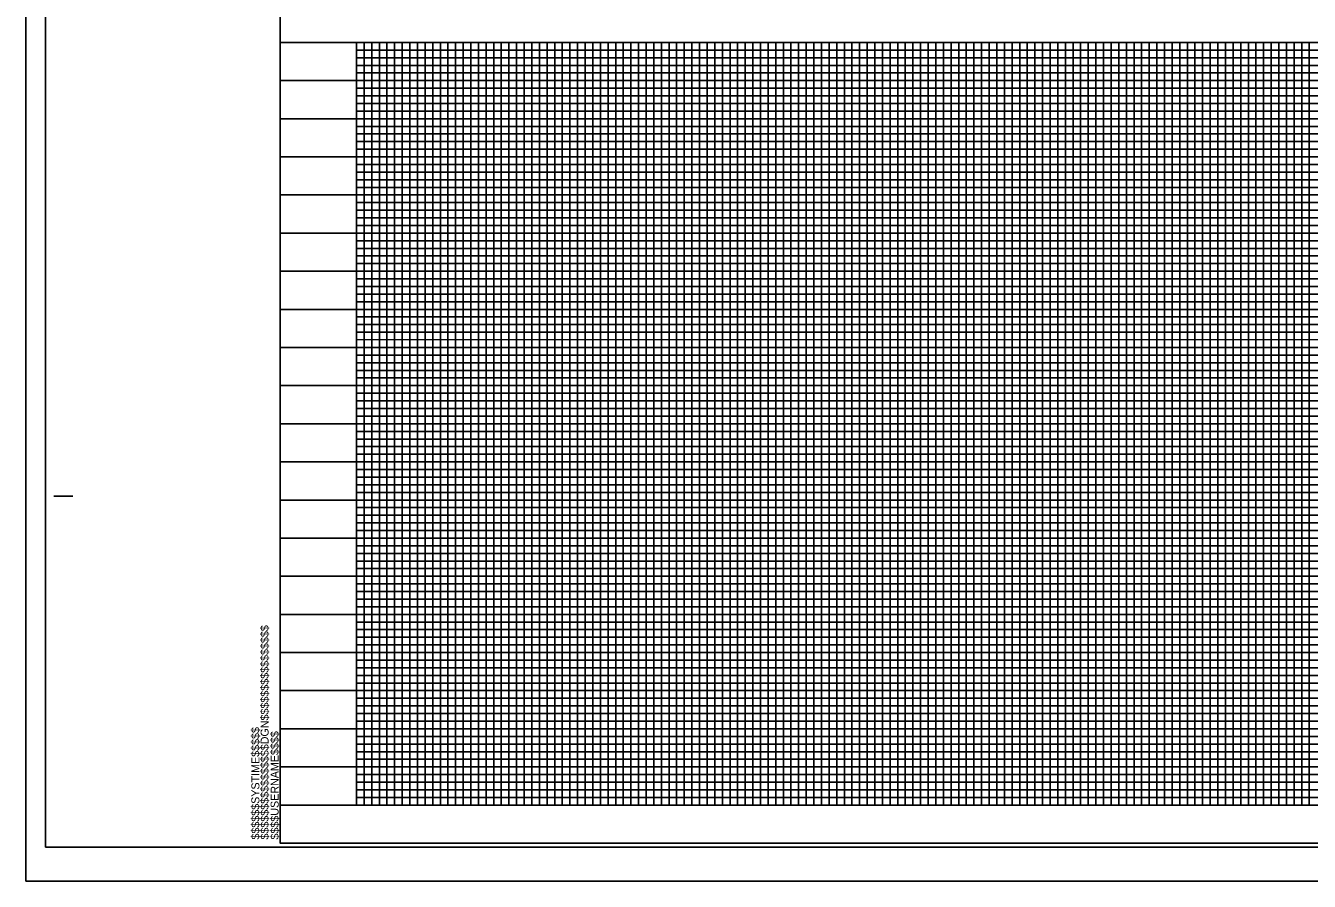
# Model space of a CAD drawing. Extents: x 2331575 to 2333259, y 609001 to 610101.
# Drawn here: x 2331575 to 2332417, y 609001 to 609562 of the extents above; entities that cross this region are included whole.
import ezdxf

# ---------------------------------------------------------------- set-up
doc = ezdxf.new("R2010")
doc.units = 0
for name, color, linetype in [('Sheet Cutting Line CELL', 7, 'Continuous'), ('Sheet DOT Grid CELL', 7, 'Continuous'), ('Sheet Layout Profile Border Port 2', 7, 'Continuous'), ('Sheet Plot Border Inside CELL', 7, 'Continuous'), ('Sheet Plot Border Outside CELL', 7, 'Continuous'), ('Sheet Profile CELL', 7, 'Continuous'), ('Sheet Profile Grid Major CELL', 7, 'Continuous'), ('Sheet Profile Grid Middle CELL', 7, 'Continuous'), ('Sheet Profile Grid Minor CELL', 7, 'Continuous')]:
    doc.layers.add(name, color=color, linetype=linetype)

msp = doc.modelspace()

# ---------------------------------------------------------------- linework, layer by layer
at = {"layer": 'Sheet Cutting Line CELL'}
for p, q in [((2331575.23, 610101.48), (2331575.23, 609001.48)), ((2331575.23, 609001.48), (2333259.23, 609001.48))]:
    msp.add_line(p, q, dxfattribs=at)
at = {"layer": 'Sheet DOT Grid CELL'}
for p, q in [((2331742.23, 609551.48), (2333242.11, 609551.48)), ((2331792.23, 609551.48), (2331792.23, 609051.48)), ((2331842.23, 609551.48), (2331842.23, 609051.48)), ((2331892.23, 609551.48), (2331892.23, 609051.48)), ((2331942.23, 609551.48), (2331942.23, 609051.48)), ((2331992.23, 609551.48), (2331992.23, 609051.48)), ((2332042.23, 609551.48), (2332042.23, 609051.48)), ((2332092.23, 609551.48), (2332092.23, 609051.48)), ((2332142.23, 609551.48), (2332142.23, 609051.48)), ((2332192.23, 609551.48), (2332192.23, 609051.48)), ((2332242.23, 609551.48), (2332242.23, 609051.48)), ((2332292.23, 609551.48), (2332292.23, 609051.48)), ((2332342.23, 609551.48), (2332342.23, 609051.48)), ((2332392.23, 609551.48), (2332392.23, 609051.48)), ((2331742.23, 609501.48), (2333242.11, 609501.48)), ((2331742.23, 609451.48), (2333242.11, 609451.48)), ((2331742.23, 609401.48), (2333242.11, 609401.48)), ((2331742.23, 609351.48), (2333242.11, 609351.48)), ((2331742.23, 609301.48), (2333242.11, 609301.48)), ((2331742.23, 609251.48), (2333242.11, 609251.48)), ((2331742.23, 609201.48), (2333242.11, 609201.48)), ((2331742.23, 609151.48), (2333242.11, 609151.48)), ((2331742.23, 609101.48), (2333242.11, 609101.48))]:
    msp.add_line(p, q, dxfattribs=at)
at = {"layer": 'Sheet Layout Profile Border Port 2'}
msp.add_lwpolyline([(2331792.23, 609551.48), (2333192.23, 609551.48), (2333192.23, 609051.48), (2331792.23, 609051.48)], close=True, dxfattribs=at)
at = {"layer": 'Sheet Plot Border Inside CELL'}
msp.add_lwpolyline([(2331588.23, 609023.93), (2333254.73, 609023.93), (2333254.73, 610079.03), (2331588.23, 610079.03)], close=True, dxfattribs=at)
at = {"layer": 'Sheet Plot Border Outside CELL'}
msp.add_lwpolyline([(2331575.23, 609001.48), (2333259.23, 609001.48), (2333259.23, 610101.48), (2331575.23, 610101.48)], close=True, dxfattribs=at)
at = {"layer": 'Sheet Profile CELL'}
for p, q in [((2331742.23, 609551.48), (2333242.23, 609551.48)), ((2331593.73, 609253.98), (2331606.23, 609253.98)), ((2333242.23, 609051.48), (2331742.23, 609051.48)), ((2331742.23, 609026.48), (2333242.23, 609026.48)), ((2331742.23, 609026.48), (2331742.23, 609026.48)), ((2331742.23, 609026.48), (2331742.23, 609026.48)), ((2331742.23, 609026.48), (2331742.23, 609026.48)), ((2331742.23, 609026.48), (2331742.23, 609026.48)), ((2331742.23, 609026.48), (2331742.23, 609026.48)), ((2331742.23, 609026.48), (2331742.23, 609026.48)), ((2331742.23, 609026.48), (2331742.23, 609026.48))]:
    msp.add_line(p, q, dxfattribs=at)
msp.add_lwpolyline([(2333242.23, 610076.48), (2331742.23, 610076.48), (2331742.23, 609026.48), (2333242.23, 609026.48)], close=True, dxfattribs=at)
msp.add_lwpolyline([(2331779.73, 609026.48), (2331779.73, 609026.48)], dxfattribs=at)
at = {"layer": 'Sheet Profile Grid Major CELL'}
for p, q in [((2332242.23, 609551.48), (2332292.23, 609551.48)), ((2332342.23, 609551.48), (2332392.23, 609551.48)), ((2331742.23, 609051.48), (2331742.23, 609051.48))]:
    msp.add_line(p, q, dxfattribs=at)
for points in [[(2331792.23, 609551.48), (2331792.23, 609051.48), (2331842.23, 609051.48), (2331842.23, 609551.48), (2331892.23, 609551.48), (2331892.23, 609051.48), (2331942.23, 609051.48), (2331942.23, 609551.48), (2331992.23, 609551.48), (2331992.23, 609051.48), (2332042.23, 609051.48), (2332042.23, 609551.48), (2332092.23, 609551.48), (2332092.23, 609051.48), (2332142.23, 609051.48), (2332142.23, 609551.48), (2332192.23, 609551.48), (2332192.23, 609051.48), (2332242.23, 609051.48), (2332242.23, 609551.48), (2332292.23, 609551.48), (2332292.23, 609051.48), (2332342.23, 609051.48), (2332342.23, 609551.48), (2332392.23, 609551.48), (2332392.23, 609051.48), (2332442.23, 609051.48)], [(2333242.23, 609501.48), (2331742.23, 609501.48)], [(2333242.23, 609451.48), (2331742.23, 609451.48), (2331742.23, 609401.48), (2333242.23, 609401.48)], [(2333242.23, 609351.48), (2331742.23, 609351.48), (2331742.23, 609301.48), (2333242.23, 609301.48)], [(2333242.23, 609251.48), (2331742.23, 609251.48), (2331742.23, 609201.48), (2333242.23, 609201.48)], [(2333242.23, 609151.48), (2331742.23, 609151.48), (2331742.23, 609151.48), (2331742.23, 609101.48), (2333242.23, 609101.48)], [(2333242.23, 609051.48), (2331742.23, 609051.48)]]:
    msp.add_lwpolyline(points, dxfattribs=at)
at = {"layer": 'Sheet Profile Grid Middle CELL'}
for points in [[(2331767.23, 609551.48), (2331817.23, 609551.48), (2331817.23, 609051.48), (2331867.23, 609051.48), (2331867.23, 609551.48), (2331917.23, 609551.48), (2331917.23, 609051.48), (2331967.23, 609051.48), (2331967.23, 609551.48), (2332017.23, 609551.48), (2332017.23, 609051.48), (2332067.23, 609051.48), (2332067.23, 609551.48), (2332117.23, 609551.48), (2332117.23, 609051.48), (2332167.23, 609051.48), (2332167.23, 609551.48), (2332217.23, 609551.48), (2332217.23, 609051.48), (2332267.23, 609051.48), (2332267.23, 609551.48), (2332317.23, 609551.48), (2332317.23, 609051.48), (2332367.23, 609051.48), (2332367.23, 609051.48), (2332367.23, 609551.48), (2332417.23, 609551.48), (2332417.23, 609051.48), (2332467.23, 609051.48)], [(2331742.23, 609526.48), (2333242.23, 609526.48)], [(2333242.23, 609476.48), (2331742.23, 609476.48), (2331742.23, 609426.48), (2333242.23, 609426.48)], [(2333242.23, 609376.48), (2331742.23, 609376.48), (2331742.23, 609326.48), (2333242.23, 609326.48)], [(2333242.23, 609276.48), (2331742.23, 609276.48), (2331742.23, 609226.48), (2333242.23, 609226.48)], [(2333242.23, 609176.48), (2331742.23, 609176.48), (2331742.23, 609126.48), (2333242.23, 609126.48)], [(2333242.23, 609076.48), (2331742.23, 609076.48)]]:
    msp.add_lwpolyline(points, dxfattribs=at)
at = {"layer": 'Sheet Profile Grid Minor CELL'}
for p, q in [((2331792.23, 609546.48), (2333192.23, 609546.48)), ((2333192.23, 609541.48), (2331792.23, 609541.48)), ((2331792.23, 609536.48), (2333192.23, 609536.48)), ((2333192.23, 609531.48), (2331792.23, 609531.48)), ((2331792.23, 609521.48), (2333192.23, 609521.48)), ((2333192.23, 609516.48), (2331792.23, 609516.48)), ((2331792.23, 609511.48), (2333192.23, 609511.48)), ((2333192.23, 609506.48), (2331792.23, 609506.48)), ((2331792.23, 609496.48), (2333192.23, 609496.48)), ((2333192.23, 609491.48), (2331792.23, 609491.48)), ((2331792.23, 609486.48), (2333192.23, 609486.48)), ((2333192.23, 609481.48), (2331792.23, 609481.48)), ((2331792.23, 609471.48), (2333192.23, 609471.48)), ((2333192.23, 609466.48), (2331792.23, 609466.48)), ((2331792.23, 609461.48), (2333192.23, 609461.48)), ((2333192.23, 609456.48), (2331792.23, 609456.48)), ((2331792.23, 609446.48), (2333192.23, 609446.48)), ((2333192.23, 609441.48), (2331792.23, 609441.48)), ((2331792.23, 609436.48), (2333192.23, 609436.48)), ((2333192.23, 609431.48), (2331792.23, 609431.48)), ((2331792.23, 609421.48), (2333192.23, 609421.48)), ((2333192.23, 609416.48), (2331792.23, 609416.48)), ((2331792.23, 609411.48), (2333192.23, 609411.48)), ((2333192.23, 609406.48), (2331792.23, 609406.48)), ((2331792.23, 609396.48), (2333192.23, 609396.48)), ((2333192.23, 609391.48), (2331792.23, 609391.48)), ((2331792.23, 609386.48), (2333192.23, 609386.48)), ((2333192.23, 609381.48), (2331792.23, 609381.48)), ((2331792.23, 609371.48), (2333192.23, 609371.48)), ((2333192.23, 609366.48), (2331792.23, 609366.48)), ((2331792.23, 609361.48), (2333192.23, 609361.48)), ((2333192.23, 609356.48), (2331792.23, 609356.63)), ((2331792.23, 609346.48), (2333192.23, 609346.48)), ((2333192.23, 609341.48), (2331792.23, 609341.48)), ((2331792.23, 609336.48), (2333192.23, 609336.48)), ((2333192.23, 609331.48), (2331792.23, 609331.48)), ((2331792.23, 609321.48), (2333192.23, 609321.48)), ((2333192.23, 609316.48), (2331792.23, 609316.48)), ((2331792.23, 609311.48), (2333192.23, 609311.48)), ((2333192.23, 609306.48), (2331792.23, 609306.48)), ((2331792.23, 609296.48), (2333192.23, 609296.48)), ((2333192.23, 609291.48), (2331792.23, 609291.48)), ((2331792.23, 609286.48), (2333192.23, 609286.48)), ((2333192.23, 609281.48), (2331792.23, 609281.48)), ((2331792.23, 609271.48), (2333192.23, 609271.48)), ((2333192.23, 609266.48), (2331792.23, 609266.48)), ((2331792.23, 609261.48), (2333192.23, 609261.48)), ((2333192.23, 609256.48), (2331792.23, 609256.48)), ((2331792.23, 609246.48), (2333192.23, 609246.48)), ((2333192.23, 609241.48), (2331792.23, 609241.48)), ((2331792.23, 609236.48), (2333192.23, 609236.48)), ((2333192.23, 609231.48), (2331792.23, 609231.48)), ((2331792.23, 609221.48), (2333192.23, 609221.48)), ((2333192.23, 609216.48), (2331792.23, 609216.48)), ((2331792.23, 609211.48), (2333192.23, 609211.48)), ((2333192.23, 609206.48), (2331792.23, 609206.48)), ((2331792.23, 609196.48), (2333192.23, 609196.48)), ((2333192.23, 609191.48), (2331792.23, 609191.48)), ((2331792.23, 609186.48), (2333192.23, 609186.48)), ((2333192.23, 609181.48), (2331792.23, 609181.48)), ((2331792.23, 609171.48), (2333192.23, 609171.48)), ((2333192.23, 609166.48), (2331792.23, 609166.48)), ((2331792.23, 609161.48), (2333192.23, 609161.48)), ((2333192.23, 609156.48), (2331792.23, 609156.48)), ((2331792.23, 609146.48), (2333192.23, 609146.48)), ((2333192.23, 609141.48), (2331792.23, 609141.48)), ((2331792.23, 609136.48), (2333192.23, 609136.48)), ((2333192.23, 609131.48), (2331792.23, 609131.48)), ((2331792.23, 609121.48), (2333192.23, 609121.48)), ((2333192.23, 609116.48), (2331792.23, 609116.48)), ((2331792.23, 609111.48), (2333192.23, 609111.48)), ((2333192.23, 609106.48), (2331792.23, 609106.48)), ((2331792.23, 609096.48), (2333192.23, 609096.48)), ((2333192.23, 609091.48), (2331792.23, 609091.48)), ((2331792.23, 609086.48), (2333192.23, 609086.48)), ((2333192.23, 609081.48), (2331792.23, 609081.48)), ((2331792.23, 609071.48), (2333192.23, 609071.48)), ((2333192.23, 609066.48), (2331792.23, 609066.48)), ((2331792.23, 609061.48), (2333192.23, 609061.48)), ((2331792.23, 609056.48), (2333192.23, 609056.48))]:
    msp.add_line(p, q, dxfattribs=at)
for points in [[(2331792.23, 609551.48), (2331797.23, 609551.48), (2331797.23, 609051.48), (2331802.23, 609051.48), (2331802.23, 609551.48), (2331807.23, 609551.48), (2331807.23, 609051.48), (2331812.23, 609051.48), (2331812.23, 609551.48), (2331822.23, 609551.48), (2331822.23, 609051.48), (2331827.23, 609051.48), (2331827.23, 609551.48), (2331832.23, 609551.48), (2331832.23, 609051.48), (2331837.23, 609051.48), (2331847.23, 609051.48), (2331852.23, 609051.48), (2331852.23, 609551.48), (2331857.23, 609551.48), (2331857.23, 609051.48), (2331862.23, 609051.48), (2331862.23, 609551.48), (2331872.23, 609551.48), (2331872.23, 609051.48), (2331877.23, 609051.48), (2331877.23, 609551.48), (2331882.23, 609551.48), (2331882.23, 609051.48), (2331887.23, 609051.48), (2331887.23, 609551.48), (2331897.23, 609551.48), (2331897.23, 609051.48), (2331902.23, 609051.48), (2331902.23, 609551.48), (2331907.23, 609551.48), (2331907.23, 609051.48), (2331912.23, 609051.48), (2331912.23, 609551.48), (2331922.23, 609551.48), (2331922.23, 609051.48), (2331927.23, 609051.48), (2331927.23, 609551.48), (2331932.23, 609551.48), (2331932.23, 609051.48), (2331937.23, 609051.48), (2331937.23, 609551.48), (2331947.23, 609551.48), (2331947.23, 609051.48), (2331952.23, 609051.48), (2331952.23, 609551.48), (2331957.23, 609551.48), (2331957.23, 609051.48), (2331962.23, 609051.48), (2331962.23, 609551.48), (2331972.23, 609551.48), (2331972.23, 609051.48), (2331977.23, 609051.48), (2331977.23, 609551.48), (2331982.23, 609551.48), (2331982.23, 609051.48), (2331987.23, 609051.48), (2331987.23, 609551.48), (2331997.23, 609551.48), (2331997.23, 609051.48), (2332002.23, 609051.48), (2332002.23, 609551.48), (2332007.23, 609551.48), (2332007.23, 609051.48)], [(2331837.23, 609051.48), (2331837.23, 609551.48), (2331847.23, 609551.48), (2331847.23, 609051.48)], [(2332007.23, 609051.48), (2332012.23, 609051.48), (2332012.23, 609551.48), (2332022.23, 609551.48), (2332022.23, 609051.48), (2332027.23, 609051.48), (2332027.23, 609551.48), (2332032.23, 609551.48), (2332032.23, 609051.48), (2332037.23, 609051.48), (2332037.23, 609551.48), (2332047.23, 609551.48), (2332047.23, 609051.48), (2332052.23, 609051.48), (2332052.23, 609551.48), (2332057.23, 609551.48), (2332057.23, 609051.48), (2332062.23, 609051.48), (2332062.23, 609551.48), (2332072.23, 609551.48), (2332072.23, 609051.48), (2332077.23, 609051.48), (2332077.23, 609551.48), (2332082.23, 609551.48), (2332082.23, 609051.48), (2332087.23, 609051.48), (2332087.23, 609551.48), (2332097.23, 609551.48), (2332097.23, 609051.48), (2332102.23, 609051.48), (2332102.23, 609551.48), (2332107.23, 609551.48), (2332107.23, 609051.48), (2332112.23, 609051.48), (2332112.23, 609551.48), (2332122.23, 609551.48), (2332122.23, 609051.48), (2332127.23, 609051.48), (2332127.23, 609551.48), (2332132.23, 609551.48), (2332132.23, 609051.48), (2332137.23, 609051.48), (2332137.23, 609551.48), (2332147.23, 609551.48), (2332147.23, 609051.48), (2332152.23, 609051.48), (2332152.23, 609551.48), (2332157.23, 609551.48), (2332157.23, 609051.48), (2332162.23, 609051.48), (2332162.23, 609551.48), (2332172.23, 609551.48), (2332172.23, 609051.48), (2332177.23, 609051.48), (2332177.23, 609551.48), (2332182.23, 609551.48), (2332182.23, 609051.48), (2332187.23, 609051.48), (2332187.23, 609551.48), (2332197.23, 609551.48), (2332197.23, 609051.48), (2332202.23, 609051.48), (2332202.23, 609551.48), (2332207.23, 609551.48), (2332207.23, 609051.48), (2332212.23, 609051.48), (2332212.23, 609551.48), (2332222.23, 609551.48), (2332222.23, 609051.48), (2332227.23, 609051.48), (2332227.23, 609551.48), (2332232.23, 609551.48), (2332232.23, 609051.48), (2332237.23, 609051.48), (2332237.23, 609551.48), (2332247.23, 609551.48), (2332247.23, 609051.48), (2332252.23, 609051.48), (2332252.23, 609551.48), (2332257.23, 609551.48), (2332257.23, 609051.48), (2332262.23, 609051.48), (2332262.23, 609551.48), (2332272.23, 609551.48), (2332272.23, 609051.48), (2332277.23, 609051.48), (2332277.23, 609551.48), (2332282.23, 609551.48), (2332282.23, 609051.48), (2332287.23, 609051.48), (2332287.23, 609551.48), (2332297.23, 609551.48), (2332297.23, 609051.48), (2332302.23, 609051.48), (2332302.23, 609551.48), (2332307.23, 609551.48), (2332307.23, 609051.48), (2332312.23, 609051.48), (2332312.23, 609551.48), (2332322.23, 609551.48)], [(2332322.23, 609551.48), (2332322.23, 609051.48), (2332327.23, 609051.48), (2332327.23, 609551.48), (2332332.23, 609551.48), (2332332.23, 609051.48), (2332337.23, 609051.48), (2332337.23, 609551.48), (2332347.23, 609551.48), (2332347.23, 609051.48), (2332352.23, 609051.48), (2332352.23, 609551.48), (2332357.23, 609551.48), (2332357.23, 609051.48), (2332362.23, 609051.48), (2332362.23, 609551.48), (2332372.23, 609551.48), (2332372.23, 609051.48), (2332377.23, 609051.48), (2332377.23, 609551.48), (2332382.23, 609551.48), (2332382.23, 609051.48), (2332387.23, 609051.48), (2332387.23, 609551.48), (2332397.23, 609551.48), (2332397.23, 609051.48), (2332402.23, 609051.48), (2332402.23, 609551.48), (2332407.23, 609551.48), (2332407.23, 609051.48), (2332412.23, 609051.48), (2332412.23, 609551.48), (2332422.23, 609551.48)]]:
    msp.add_lwpolyline(points, dxfattribs=at)

# ---------------------------------------------------------------- texts
at = {"layer": 'Sheet Profile CELL'}
for s, p in [('$$$$$$$$$$$$$$$$DGN$$$$$$$$$$$$$$$$', (2331734.59, 609028.85)), ('$$$$$$SYSTIME$$$$$', (2331728.54, 609028.85)), ('$$$$USERNAME$$$$', (2331741.16, 609028.87))]:
    msp.add_text(s, height=5.25, rotation=90, dxfattribs=at).set_placement(p)

doc.saveas('drawing.dxf')
